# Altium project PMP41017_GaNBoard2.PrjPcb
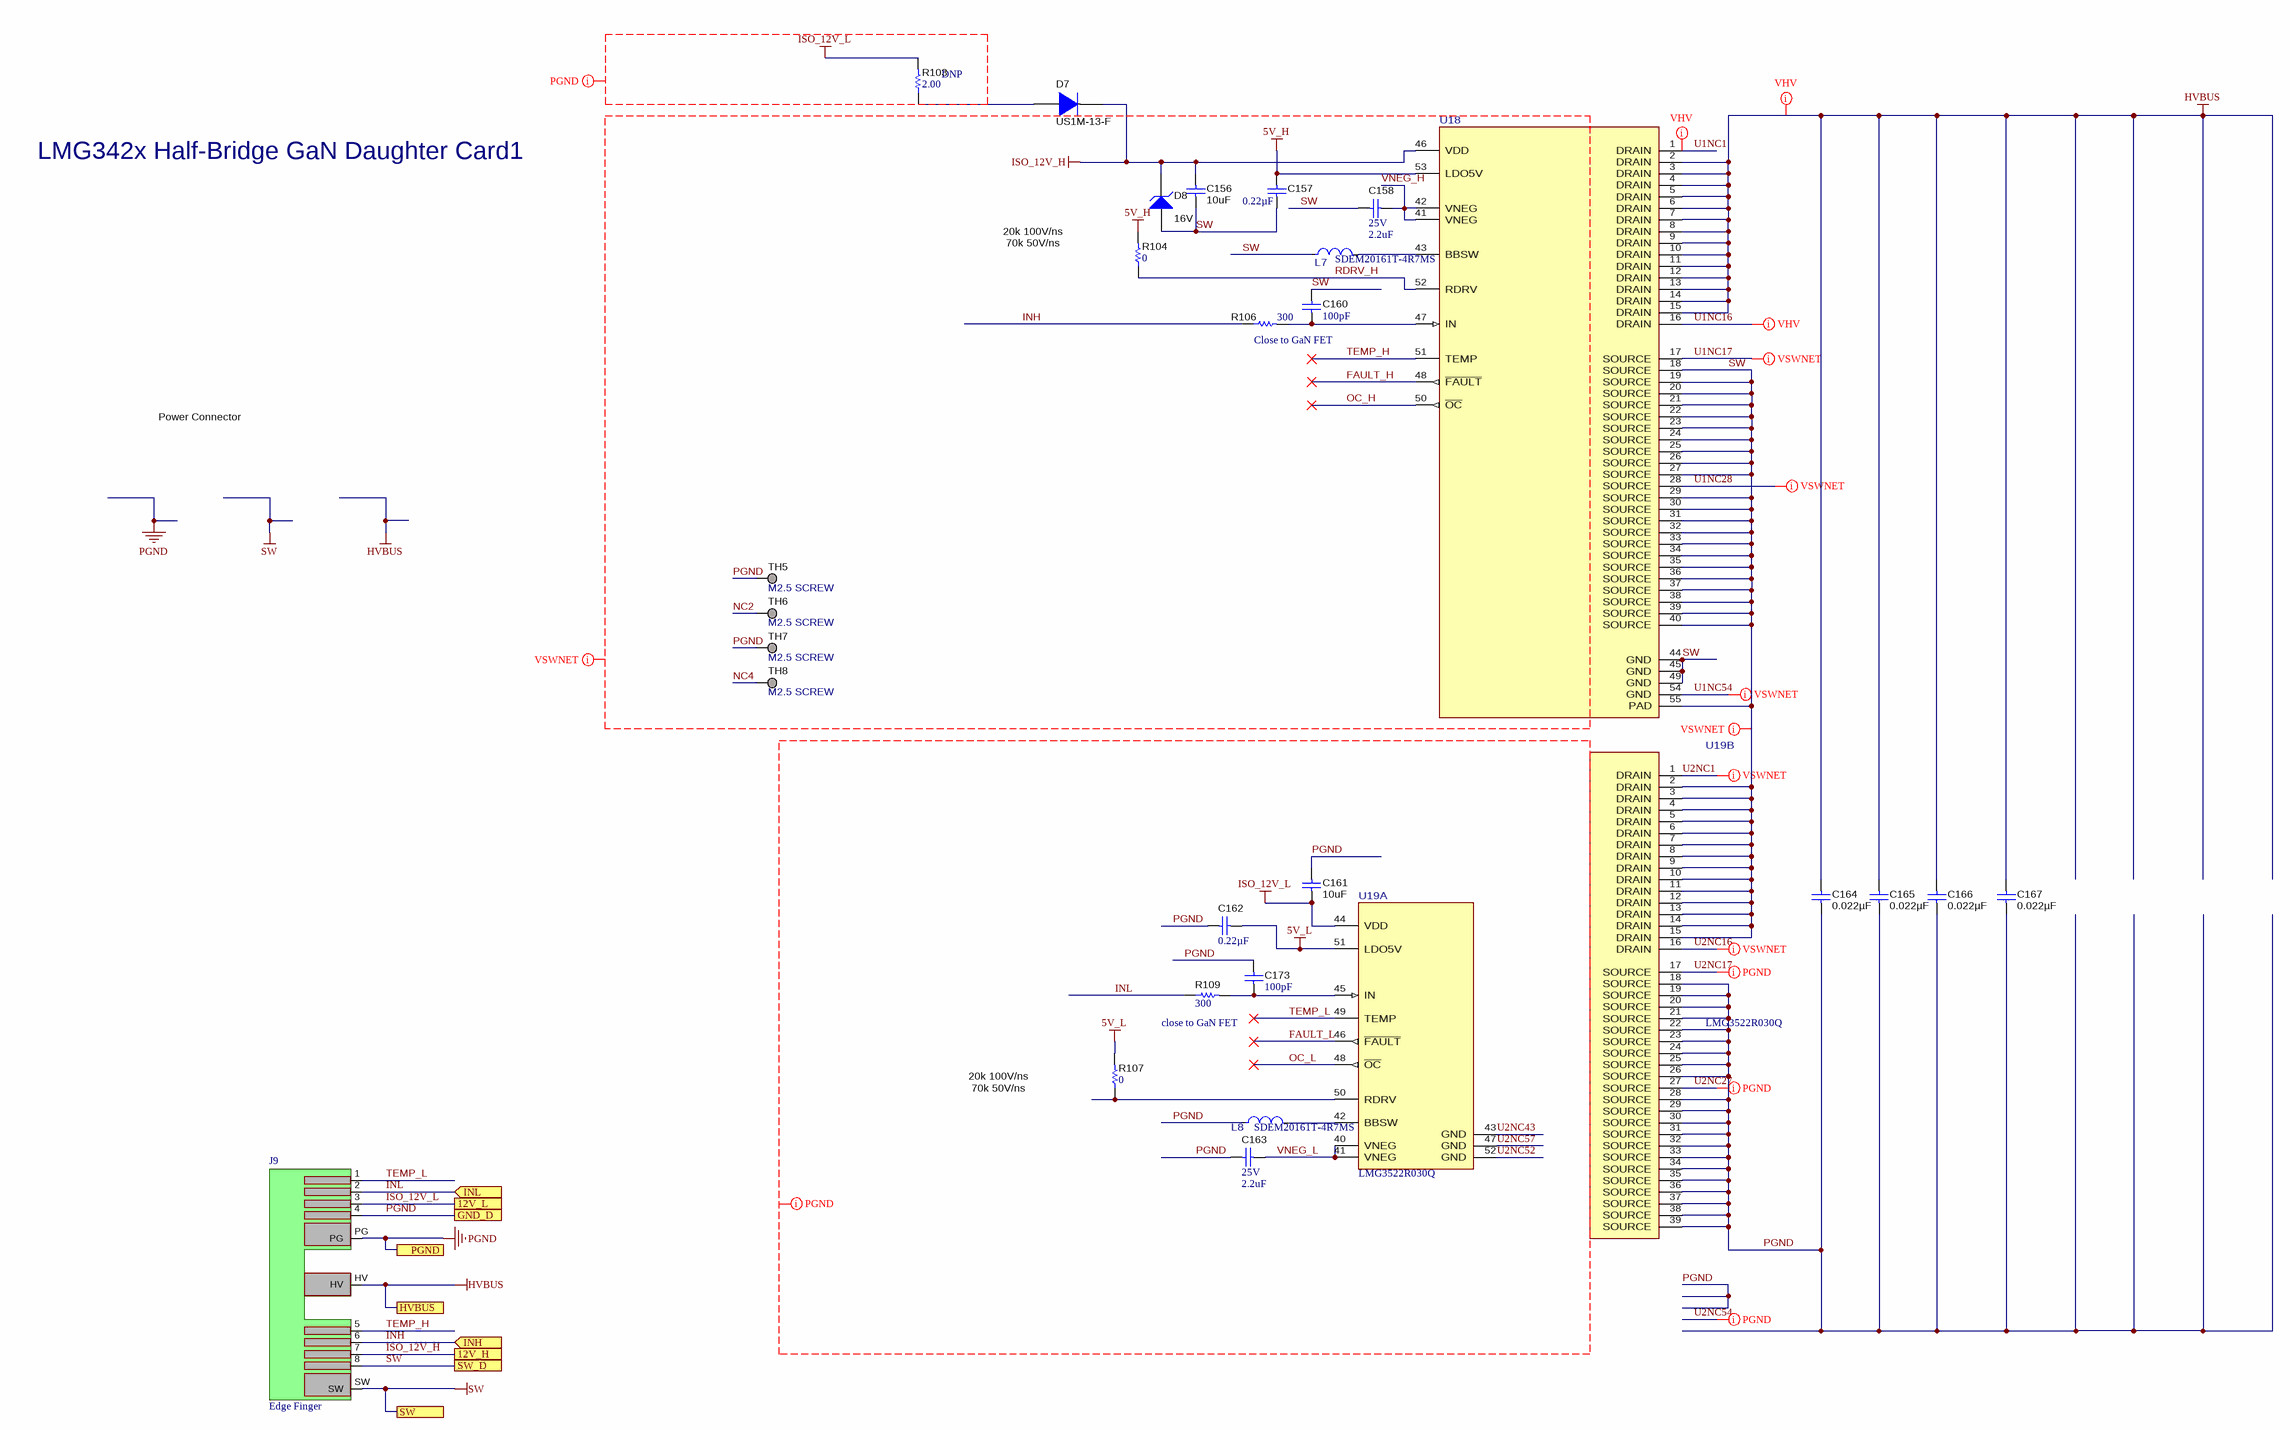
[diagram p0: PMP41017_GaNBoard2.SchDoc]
CopyrightYear: 2022; PCB_Layout: Desheng Guo; PCB_Rev: E1; PRJ_Customer: Public Release; PRJ_Engineer: Desheng Guo; PRJ_Number: PMP41017; PRJ_Title: CRPS 12V 3000W LLC; SCH_Rev: E1; TechSupport: http://www.ti.com/support; TID: N/A
1 sheet, 28 parts. Net scope: flat (ports and power ports of the same name join across sheets).
Board file: PMP41017_GaNBoard2.PcbDoc

## Sheet PMP41017_GaNBoard2.SchDoc
size A2; Date: Not shown in title block; ApprovedBy: Not shown in title block; CheckedBy: Not shown in title block; Author: Not shown in title block; CompanyName: Not shown in title block; Engineer: Not shown in title block; Organization: Not shown in title block; Address1: Not shown in title block; Address2: Not shown in title block; Address3: Not shown in title block; Address4: Not shown in title block; DocumentNumber: 1; Revision: Use project parameter SCH_Rev; SheetNumber: 2; SheetTotal: 2; PageSetup: Record=PageOptions¦CenterHorizontal=True¦CenterVertical=True¦PrintScale=0.69¦XCorrection=1.00¦YCorrection=1.00¦PrintKind=0¦BorderSize=5000000¦LeftOffset=0¦BottomOffset=0¦Orientation=2¦PaperLength=1000¦PaperWidth=1000¦Scale=100¦PaperSource=15¦PrintQuality=600¦MediaType=1¦DitherType=10¦PaperKind=Letter¦PrintScaleMode=1

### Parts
C156  ValueDisplayed: 10uF  [1206_190]  (hidden comment: C1206C106K3RACTU)
C157  ValueDisplayed: 0.22µF  [0402]  (hidden comment: CL05B224KO5NNNC)
C158  VDC_V: 25V  ValueDisplayed: 2.2uF  [0805_HV]  (hidden comment: GRM219R61E225KA12D)
C160  ValueDisplayed: 100pF  [0402]  (hidden comment: 885012205055)
C161  ValueDisplayed: 10uF  [1206_190]  (hidden comment: C1206C106K3RACTU)
C162  ValueDisplayed: 0.22µF  [0402]  (hidden comment: CL05B224KO5NNNC)
C163  VDC_V: 25V  ValueDisplayed: 2.2uF  [0805_HV]  (hidden comment: GRM219R61E225KA12D)
C164  ValueDisplayed: 0.022µF  [1206_190]  (hidden comment: C1206C223KDRACTU)
C165  ValueDisplayed: 0.022µF  [1206_190]  (hidden comment: C1206C223KDRACTU)
C166  ValueDisplayed: 0.022µF  [1206_190]  (hidden comment: C1206C223KDRACTU)
C167  ValueDisplayed: 0.022µF  [1206_190]  (hidden comment: C1206C223KDRACTU)
C173  ValueDisplayed: 100pF  [0402]  (hidden comment: 885012205055)
D7  US1M-13-F  [SMA]
D8  value 16V  [SOD-123]  (hidden comment: BZT52C16-7-F)
J9  Edge Finger  [EC_GaN_DC_HBLLC]  (no BOM)
L7  SDEM20161T-4R7MS  [FP-SDEM20161T-4R7MS_SMD2-MFG]  (value not drawn)
L8  SDEM20161T-4R7MS  [FP-SDEM20161T-4R7MS_SMD2-MFG]  (value not drawn)
R103  ValueDisplayed: 2.00  [0603]  (hidden comment: MCT06030C2008FP500)
R104  ValueDisplayed: 0  [0402]  (hidden comment: MCR01MZPJ000)
R106  ValueDisplayed: 300  [0402]  (hidden comment: CRCW0402300RJNED)
R107  ValueDisplayed: 0  [0402]  (hidden comment: MCR01MZPJ000)
R109  ValueDisplayed: 300  [0402]  (hidden comment: CRCW0402300RJNED)
TH5  M2.5 SCREW  [TP_H045P075]
TH6  M2.5 SCREW  [TP_H045P075]
TH7  M2.5 SCREW  [TP_H045P075]
TH8  M2.5 SCREW  [TP_H045P075]
U18  LMG3422R030RQZT  [RQZ0054A-MFG-NV]  (value not drawn)
U19  LMG3522R030Q  [RQS0052A-MFG]  (parts A,B of 2)

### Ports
12V_H, 12V_L, GND_D, HVBUS, INH (in), INL (in), PGND, SW, SW_D

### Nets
5V_H: C157.1 R104.2 U18.53(LDO5V)
5V_L: C162.2 R107.2 U19.51(LDO5V)
HVBUS: C164.1 C165.1 C166.1 C167.1 J9.HV U18.2(DRAIN) U18.3(DRAIN) U18.4(DRAIN) U18.5(DRAIN) U18.6(DRAIN) U18.7(DRAIN) U18.8(DRAIN) U18.9(DRAIN) U18.10(DRAIN) U18.11(DRAIN) U18.12(DRAIN) U18.13(DRAIN) U18.14(DRAIN) U18.15(DRAIN) ; port HVBUS
ISO_12V_H: C156.1 D7.1(K) D8.1(K) J9.7 U18.46(VDD) ; port 12V_H
ISO_12V_L: C161.2 J9.3 R103.2 U19.44(VDD) ; port 12V_L
PGND: C161.1 C162.1 C163.2 C164.2 C165.2 C166.2 C167.2 C173.1 J9.4 J9.PG L8.1 TH5.1 TH7.1 U19.18(SOURCE) U19.19(SOURCE) U19.20(SOURCE) U19.21(SOURCE) U19.22(SOURCE) U19.23(SOURCE) U19.24(SOURCE) U19.25(SOURCE) U19.26(SOURCE) U19.28(SOURCE) U19.29(SOURCE) U19.30(SOURCE) U19.31(SOURCE) U19.32(SOURCE) U19.33(SOURCE) U19.34(SOURCE) U19.35(SOURCE) U19.36(SOURCE) U19.37(SOURCE) U19.38(SOURCE) U19.39(SOURCE) ; port GND_D, port PGND
SW: C156.2 C157.2 C158.2 C160.1 D8.2(A) J9.8 J9.SW L7.1 U18.18(SOURCE) U18.19(SOURCE) U18.20(SOURCE) U18.21(SOURCE) U18.22(SOURCE) U18.23(SOURCE) U18.24(SOURCE) U18.25(SOURCE) U18.26(SOURCE) U18.27(SOURCE) U18.29(SOURCE) U18.30(SOURCE) U18.31(SOURCE) U18.32(SOURCE) U18.33(SOURCE) U18.34(SOURCE) U18.35(SOURCE) U18.36(SOURCE) U18.37(SOURCE) U18.38(SOURCE) U18.39(SOURCE) U18.40(SOURCE) U18.44(GND) U18.45(GND) U18.49(GND) U18.55(PAD) U19.2(DRAIN) U19.3(DRAIN) U19.4(DRAIN) U19.5(DRAIN) U19.6(DRAIN) U19.7(DRAIN) U19.8(DRAIN) U19.9(DRAIN) U19.10(DRAIN) U19.11(DRAIN) U19.12(DRAIN) U19.13(DRAIN) U19.14(DRAIN) U19.15(DRAIN) ; port SW, port SW_D
FAULT_H: U18.48(~{FAULT})  [project net FAULT_H_2]
FAULT_L: U19.46(~{FAULT})  [project net FAULT_L_2]
INH: J9.6 R106.1 ; port INH
INL: J9.2 R109.1 ; port INL
NC2: TH6.1  [project net NC2_2]
NC4: TH8.1  [project net NC4_2]
OC_H: U18.50(~{OC})  [project net OC_H_2]
OC_L: U19.48(~{OC})  [project net OC_L_2]
RDRV_H: R104.1 U18.52(RDRV)  [project net RDRV_H_2]
TEMP_H: J9.5 U18.51(TEMP)  [project net TEMP_H_2]
TEMP_L: J9.1 U19.49(TEMP)  [project net TEMP_L_2]
U1NC1: U18.1(DRAIN)  [project net U1NC1_2]
U1NC16: U18.16(DRAIN)  [project net U1NC16_2]
U1NC17: U18.17(SOURCE)  [project net U1NC17_2]
U1NC28: U18.28(SOURCE)  [project net U1NC28_2]
U1NC54: U18.54(GND)  [project net U1NC54_2]
U2NC1: U19.1(DRAIN)  [project net U2NC1_2]
U2NC16: U19.16(DRAIN)  [project net U2NC16_2]
U2NC17: U19.17(SOURCE)  [project net U2NC17_2]
U2NC27: U19.27(SOURCE)  [project net U2NC27_2]
U2NC43: U19.43(GND)  [project net U2NC43_2]
U2NC52: U19.52(GND)  [project net U2NC52_2]
U2NC57: U19.47(GND)  [project net U2NC57_2]
VNEG_H: C158.1 U18.41(VNEG) U18.42(VNEG)  [project net VNEG_H_2]
VNEG_L: C163.1 U19.40(VNEG) U19.41(VNEG)  [project net VNEG_L_2]
NetC160_2: C160.2 R106.2 U18.47(IN)
NetC173_2: C173.2 R109.2 U19.45(IN)
NetD7_2: D7.2(A) R103.1
NetL7_2: L7.2 U18.43(BBSW)
NetL8_2: L8.2 U19.42(BBSW)
NetR107_1: R107.1 U19.50(RDRV)

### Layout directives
net class VSWNET: 5V_H, FAULT_H, INH, ISO_12V_H, NC2, NC4, OC_H, PGND, RDRV_H, SW, TEMP_H, U1NC17_2, U1NC28_2, U1NC54_2, U2NC1_2, U2NC16_2, VNEG_H
net class VHV: HVBUS, U1NC1_2, U1NC16_2
net class PGND: 5V_L, FAULT_L, INL, ISO_12V_L, OC_L, PGND, TEMP_L, U2NC17_2, U2NC27_2, U2NC43, U2NC52, U2NC54_2, U2NC57, VNEG_L

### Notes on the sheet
- (near R103) DNP
- LMG342x Half-Bridge GaN Daughter Card1
- 20k 100V/ns
- 70k 50V/ns
- (near L7) SDEM20161T-4R7MS
- (near R106) Close to GaN FET
- Power Connector
- close to GaN FET
- (near L8) SDEM20161T-4R7MS

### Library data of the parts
C156 C161 = CMP-0008589-2: CAP, CERM, 10 uF, 25 V, +/- 10%, X7R, 1206_190; Manufacturer: Kemet; Polarized: N; Value: 10uF; U/M: EA; Cap_F: 10µF; Value1: Unknown; VDC_V: 25V; TaMin_C: -55°C; TaMax_C: 125°C; Cap_Case: 1206; SizeArea_mm2: 5.12; SizeAreaWB_mm2: 10.92; SizeX_mm: 3.2; SizeY_mm: 1.6; SizeZ_mm: 1.9; AEC Category: Q200
C157 C162 = CMP-0860563-1: CAP, CERM, 0.22 µF, 16 V,+/- 10%, X7R, 0402; Manufacturer: Samsung Electro-Mechanics; SizeX_mm: 1; Green_REACh: Incomplete; TaMin_C: -55°C; SizeArea_mm2: 0.5; TaMax_C: 125°C; U/M: EA; Green_Lifecycle: Active; SizeAreaWB_mm2: 3; VDC_V: 16V; AEC Qualified: N; SizeZ_mm: 0.6; AEC Category: Q200; Cap_F: 220nF; Value: 0.22uF
C158 C163 = CMP-0008208-1: CAP, CERM, 2.2 uF, 25 V, +/- 10%, X5R, 0805; Manufacturer: MuRata; TaMin_C: -55°C; ESR_ohm: 6m; Polarized: N; SizeAreaWB_mm2: 6.75; Value1: 0.006 ohm; U/M: EA; Value: 2.2uF; TaMax_C: 85°C; SizeZ_mm: 1.45; SizeX_mm: 2; SizeY_mm: 1.25; Cap_Case: 0805; SizeArea_mm2: 2.5; Cap_F: 2.2µF; AEC Category: Q200
C160 C173 = CMP-0006230-2: CAP, CERM, 100 pF, 50 V, +/- 10%, X7R, 0402; Manufacturer: Wurth Elektronik; Polarized: N; Value: 100pF; U/M: EA; Value1: Unknown; VDC_V: 50V; TaMin_C: -55°C; TaMax_C: 125°C; AEC Category: Q200; SizeArea_mm2: 0.5; SizeAreaWB_mm2: 3; SizeX_mm: 1; SizeZ_mm: 0.6
C164-C167 = CMP-0084048-1: CAP, CERM, 0.022 µF, 1000 V,+/- 10%, X7R, AEC-Q200 Grade 1, 1206; Manufacturer: Kemet; Polarized: N; CompType: Capacitor; Value: 0.022uF; U/M: EA; Cap_F: 22nF; VDC_V: 1kV; Value2: 1000V; TaMin_C: -55°C; TaMax_C: 125°C; Cap_Case: 1206; SizeArea_mm2: 5.12; SizeAreaWB_mm2: 10.92; SizeX_mm: 3.2; SizeY_mm: 1.6; SizeZ_mm: 1.9; AEC Category: Q200; AEC Qualified: Y; AEC Grade: 1
D7 = CMP-0076882-1: Diode, Ultrafast, 1000 V, 1 A, SMA; Manufacturer: Diodes Inc.; SizeAreaWB_mm2: 37.3428; Vr_V: 1kV; SizeArea_mm2: 16.3228; TJmax_C: 150°C; AEC Category: Q101; Value: 1000V; SizeZ_mm: 2.87; Green_REACh: Incomplete; Io_A: 1A; Vf_V: 1.7V; SizeY_mm: 2.92; Green_Lifecycle: Not Set; U/M: EA; SizeX_mm: 5.59; RJC_CperW: 30.0
D8 = CMP-0005769-2: Diode, Zener, 16 V, 500 mW, AEC-Q101, SOD-123; Manufacturer: Diodes Inc.; Power_W: 500mW; SizeAreaWB_mm2: 13.095; Value1: 0.5W; RJA_CperW: 338; U/M: EA; SizeZ_mm: 1.35; SizeX_mm: 3.85; SizeY_mm: 1.7; SizeArea_mm2: 6.545; AEC Qualified: Y; AEC Category: Q101
J9 = EC_GaN
L7 L8 = CMP-0089347-1: 4.7µH Unshielded Inductor 1.1A 426mOhm Max 0806 (2016 Metric); Manufacturer: Cyntec; AEC Qualified: No; Material: Metal Dust; Isat: 1.26A; Test Frequency: 1MHz; DCR_ohm: 0.426; SizeZ_mm: 1mm; Tolerance_%: 20%
R103 = CMP-0022732-2: RES, 2.00, 1%, 0.125 W, 0603; Manufacturer: Vishay/Beyschlag; Power_W: 125mW; TempCo: 50 ppm/C; Value_Code: 2R00; U/M: EA; Value: 2.00; EIA_Code: E96; Res_ohm: 2; SizeX_mm: 1.6; SizeY_mm: 0.8; Value2: 0.125W; SizeArea_mm2: 1.28; AEC Qualified: N; AEC Category: Q200; SizeZ_mm: 1
R104 R107 = CMP-0027002-2: RES, 0, 5%, 0.063 W, 0402; Manufacturer: Rohm; Power_W: 63mW; TempCo: 500 ppm/C; Value_Code: 0000; U/M: EA; Value: 0; EIA_Code: E24; SizeX_mm: 1; SizeY_mm: 0.5; SizeZ_mm: 0.6; Value2: 0.063W; VDC_V: 50V; AEC Category: Q200
R106 R109 = CMP-0026902-3: RES, 300, 5%, 0.063 W, AEC-Q200 Grade 0, 0402; Manufacturer: Vishay-Dale; Power_W: 63mW; TempCo: 200 ppm/C; Value_Code: 300R; Value: 300; EIA_Code: E24; SizeX_mm: 1; SizeY_mm: 0.5; SizeZ_mm: 0.6; Value2: 0.063W; AEC Qualified: Y; VDC_V: 50V; AEC Category: Q200; AEC Grade: 0
TH5-TH8 = CMP-0003719-1: Screws, M2.5x0.45 thread, L4.0mm, Steel; Manufacturer: Keystone Electronics; PartNumber: 29300; CompType: Pad
U18 = CMP-0088545-3: 600-V 30-mΩ Integrated GaN Power Stage with Smart Driver; Manufacturer: Texas Instruments; Standoff Height: 0mm; TJmax_C: +125°C; Number Of Outputs: 1; Nominal Supply Current: 13mA; Max Supply Voltage: 18V; Min Supply Voltage: 7.5V; SizeZ_mm: 0.9mm; Output Voltage: 480V; AEC Qualified: No; AEC Category: Q200; CompType: IC
U19 = CMP-0089967-1: 650-V 30-mΩ GaN FET with Integrated Driver and Protection; Manufacturer: Texas Instruments; Standoff Height: 0mm; SizeZ_mm: 1mm; Nominal Supply Current: 16mA; Max Supply Voltage: 18V; Min Supply Voltage: 7.5V; AEC Grade: Grade 1; AEC Qualified: Yes; Output Voltage: 520V; Number Of Outputs: 1; TJmax_C: +125°C

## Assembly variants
001: not fitted FID1 FID2 FID3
